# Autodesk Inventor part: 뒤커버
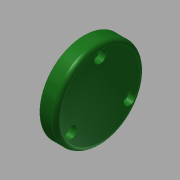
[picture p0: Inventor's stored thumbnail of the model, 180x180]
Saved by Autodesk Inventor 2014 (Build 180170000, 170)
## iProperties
Created: 2015-11
Part Number: 뒤커버
Material: 알루미늄 6061
Document SubType Name: Modeling
Designer: mduedu
Density: 1 g/cm^3
Appearance: 매끄러움 - 짙은 산림 녹색
Author: mduedu
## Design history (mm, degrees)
sketch "스케치5"
  geometry: C1 r 30 at (0, 0); 2 further points
  constraints: 2 coincident, 1 centre point
  dimensions: "d66" = 60 diameter of C1
extrude "돌출2" new body sketch "스케치5" distance "d67" = 11; taper "d68" = 0 deg
sketch "스케치6"
  geometry: C1 r 16 at (0, 0); 1 further point
  constraints: 1 centre point, 1 coincident
  dimensions: "d69" = 32 diameter of C1
extrude "돌출3" join sketch "스케치6" distance "d70" = 3; taper "d71" = 0 deg
hole "구멍5" diameter "d74" = 25; stored, may be unused: countersink angle "d78" = 90 deg, drill point angle "d80" = 0 deg; dims "d72" = 10, "d73" = 10, "d75" = 6, "d76" = 4, "d77" = 2, "d79" = 10
fillet "모깎기8" dims "d82" = 3
fillet "모깎기9" dims "d83" = 3
fillet "모깎기10" dims "d84" = 0.3
sketch "스케치7" dims "d85" = 46
  geometry: 3 further points
  constraints: 2 vertical alignment, 1 coincident, 2 other
hole "구멍6" sketch "스케치7" at (0, 23) diameter "d86" = 4.5; stored, may be unused: countersink angle "d90" = 90 deg, drill point angle "d92" = 0 deg; dims "d87" = 6, "d88" = 8, "d89" = 4.6, "d91" = 10
node "솔리드2"
pattern_circular "원형 패턴3" dims angle "d94" = 360 deg
